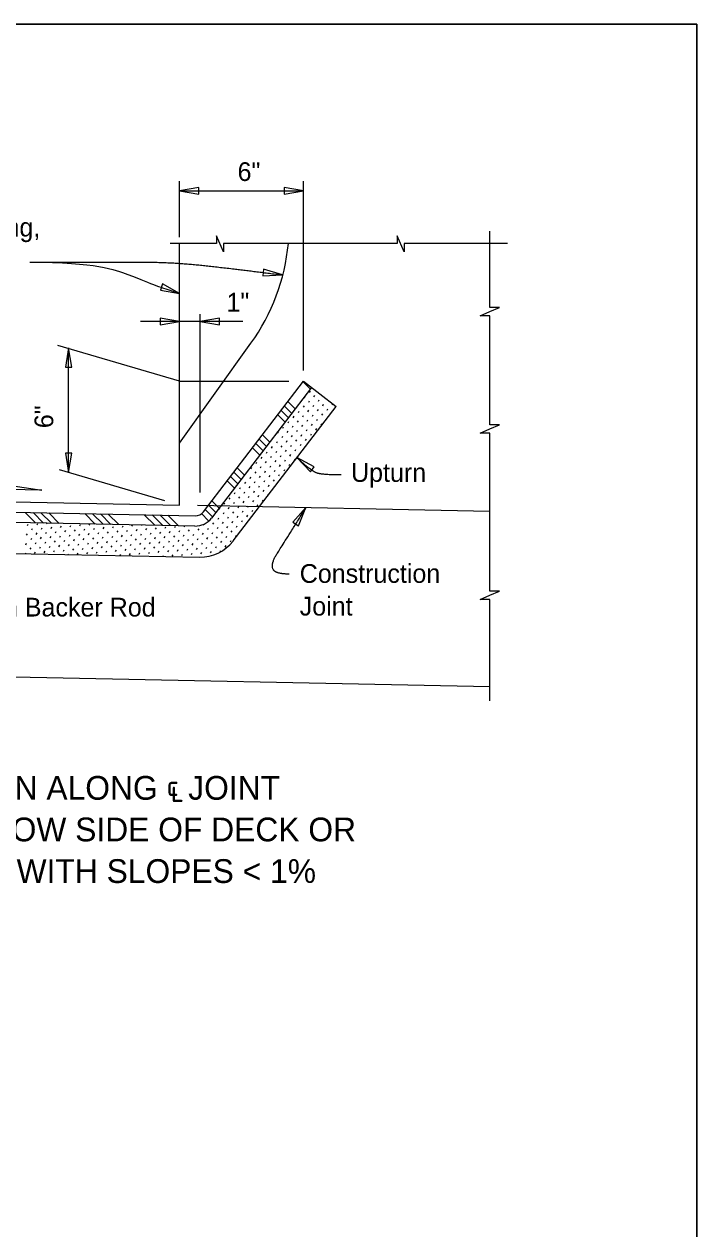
# Model space of a CAD drawing. Extents: x 0 to 15.4, y 0 to 9.7.
# Drawn here: x 12.677 to 15.394, y 4.865 to 9.73 of the extents above; entities that cross this region are included whole.
import ezdxf

# ---------------------------------------------------------------- set-up
doc = ezdxf.new("R2010")
doc.units = 0
for name, color, linetype in [('Dimension', 7, 'Continuous'), ('Miscellaneous', 7, 'Continuous'), ('Miscellaneous1', 7, 'Continuous'), ('SupstrConc', 7, 'Continuous'), ('SupstrConc_h', 7, 'Continuous'), ('TextStructures', 7, 'Continuous')]:
    doc.layers.add(name, color=color, linetype=linetype)

msp = doc.modelspace()

# ---------------------------------------------------------------- linework, layer by layer
at = {"layer": 'Dimension'}
for p, q in [((13.3048, 8.8701), (13.3048, 9.0961)), ((13.3049, 9.0564), (13.8048, 9.0564)), ((13.8048, 8.3308), (13.8048, 9.0961)), ((13.5599, 8.5291), (13.1464, 8.5291)), ((13.3883, 7.8384), (13.3883, 8.5587)), ((13.3048, 8.2874), (12.8133, 8.4319)), ((12.8566, 7.9192), (12.8566, 8.423)), ((13.3048, 8.2874), (13.7463, 8.2874)), ((13.2445, 7.8052), (12.8198, 7.93))]:
    msp.add_line(p, q, dxfattribs=at)
for points in [[(13.3048, 9.0563), (13.3829, 9.0431), (13.3829, 9.0696)], [(13.8048, 9.0563), (13.7267, 9.0696), (13.7267, 9.0431)], [(13.7197, 8.7169), (13.644, 8.74), (13.6406, 8.7137)], [(13.3048, 8.6416), (13.2361, 8.681), (13.227, 8.6561)], [(13.3048, 8.5291), (13.2267, 8.5423), (13.2267, 8.5159)], [(13.3881, 8.5291), (13.4662, 8.5159), (13.4662, 8.5423)], [(12.8565, 8.423), (12.8433, 8.3449), (12.8697, 8.3449)], [(12.8565, 7.9192), (12.8697, 7.9973), (12.8433, 7.9973)], [(13.7786, 7.9792), (13.8328, 7.9214), (13.8488, 7.9425)], [(13.8152, 7.7772), (13.7625, 7.7181), (13.7849, 7.704)]]:
    msp.add_lwpolyline(points, close=True, dxfattribs=at)
for points in [[(13.9956, 8.8435), (13.4825, 8.8435), (13.4825, 8.8104), (13.4542, 8.8744), (13.4542, 8.8435), (13.2667, 8.8435)], [(14.6286, 8.8435), (14.2115, 8.8435), (14.2115, 8.8104), (14.1831, 8.8744), (14.1831, 8.8435), (13.9956, 8.8435)], [(14.5575, 8.3416), (14.5575, 8.5521), (14.5188, 8.5521), (14.5575, 8.569), (14.5963, 8.5858), (14.5575, 8.5858), (14.5575, 8.893)], [(14.5575, 7.8014), (14.5575, 8.0783), (14.5188, 8.0783), (14.5575, 8.0952), (14.5963, 8.1121), (14.5575, 8.1121), (14.5575, 8.3416)], [(12.3088, 7.8559), (12.3453, 7.9083), (12.7488, 7.8484), (11.5452, 7.8725)], [(14.5575, 6.9971), (14.5575, 7.4067), (14.5188, 7.4067), (14.5575, 7.4235), (14.5963, 7.4404), (14.5575, 7.4404), (14.5575, 7.8014)]]:
    msp.add_lwpolyline(points, dxfattribs=at)
for points, degree in [([(12.6999, 8.7689), (13.0172, 8.7689), (13.2759, 8.7689), (13.529, 8.7414), (13.7197, 8.7169)], 2), ([(12.6999, 8.7689), (12.9693, 8.7674), (13.1155, 8.7122), (13.2151, 8.67), (13.2581, 8.6581), (13.3048, 8.6416)], 3), ([(13.9576, 7.9093), (13.886, 7.9093), (13.8377, 7.9228), (13.7786, 7.9791)], 2), ([(13.7473, 7.509), (13.6887, 7.509), (13.6736, 7.5524), (13.7227, 7.6299), (13.8153, 7.7772)], 2)]:
    msp.add_open_spline(points, degree=degree, dxfattribs=at)
at = {"layer": 'Miscellaneous'}
for p, q in [((13.4011, 7.7608), (13.8049, 8.2874)), ((13.8036, 8.2858), (13.8334, 8.2561)), ((13.8049, 8.2874), (13.9372, 8.186)), ((13.838, 8.262), (13.4342, 7.7354)), ((13.8087, 8.2211), (13.812, 8.2267)), ((13.8297, 8.242), (13.8329, 8.2476)), ((13.8474, 8.2243), (13.8507, 8.2299)), ((13.5205, 7.6426), (13.9372, 8.186)), ((13.7284, 8.1877), (13.7581, 8.1579)), ((13.7419, 8.2053), (13.7717, 8.1756)), ((13.8055, 8.1824), (13.8087, 8.188)), ((13.8265, 8.2034), (13.8297, 8.209)), ((13.8442, 8.1857), (13.8474, 8.1913)), ((13.8619, 8.1679), (13.8651, 8.1735)), ((13.8651, 8.2066), (13.8684, 8.2122)), ((13.8828, 8.1889), (13.8861, 8.1945)), ((13.9006, 8.1712), (13.9038, 8.1768)), ((13.9038, 8.2099), (13.9045, 8.211)), ((13.9215, 8.1921), (13.9239, 8.1962)), ((13.7013, 8.1524), (13.7311, 8.1226)), ((13.7149, 8.17), (13.7446, 8.1403)), ((13.7426, 8.1195), (13.7459, 8.1251)), ((13.7636, 8.1405), (13.7668, 8.1461)), ((13.7813, 8.1228), (13.7846, 8.1284)), ((13.7846, 8.1615), (13.7878, 8.1671)), ((13.8023, 8.1437), (13.8055, 8.1493)), ((13.82, 8.126), (13.8232, 8.1316)), ((13.8232, 8.1647), (13.8265, 8.1703)), ((13.8409, 8.147), (13.8442, 8.1526)), ((13.8586, 8.1293), (13.8619, 8.1349)), ((13.8796, 8.1502), (13.8828, 8.1558)), ((13.7007, 8.0776), (13.704, 8.0832)), ((13.7217, 8.0986), (13.7249, 8.1042)), ((13.7394, 8.0809), (13.7426, 8.0865)), ((13.7604, 8.1018), (13.7636, 8.1074)), ((13.7781, 8.0841), (13.7813, 8.0897)), ((13.799, 8.1051), (13.8023, 8.1107)), ((13.8167, 8.0874), (13.82, 8.093)), ((13.8377, 8.1083), (13.8409, 8.1139)), ((13.8554, 8.0906), (13.8586, 8.0962)), ((13.8764, 8.1116), (13.8796, 8.1172)), ((13.6125, 8.0366), (13.6423, 8.0068)), ((13.6261, 8.0542), (13.6558, 8.0245)), ((13.6396, 8.0719), (13.6694, 8.0421)), ((13.6975, 8.039), (13.7007, 8.0446)), ((13.7184, 8.0599), (13.7217, 8.0655)), ((13.7362, 8.0422), (13.7394, 8.0478)), ((13.7539, 8.0245), (13.7571, 8.0301)), ((13.7571, 8.0632), (13.7604, 8.0688)), ((13.7748, 8.0454), (13.7781, 8.051)), ((13.7925, 8.0277), (13.7958, 8.0333)), ((13.7958, 8.0664), (13.799, 8.072)), ((13.8135, 8.0487), (13.8167, 8.0543)), ((13.8345, 8.0696), (13.8377, 8.0752)), ((13.599, 8.0189), (13.6287, 7.9892)), ((13.6346, 7.9761), (13.6379, 7.9817)), ((13.6556, 7.9971), (13.6588, 8.0027)), ((13.6733, 7.9793), (13.6765, 7.9849)), ((13.6765, 8.018), (13.6798, 8.0236)), ((13.6942, 8.0003), (13.6975, 8.0059)), ((13.712, 7.9826), (13.7152, 7.9882)), ((13.7152, 8.0213), (13.7184, 8.0268)), ((13.7329, 8.0035), (13.7362, 8.0091)), ((13.7506, 7.9858), (13.7539, 7.9914)), ((13.7716, 8.0068), (13.7748, 8.0124)), ((13.5373, 7.9384), (13.567, 7.9087)), ((13.5927, 7.9342), (13.596, 7.9398)), ((13.6137, 7.9551), (13.6169, 7.9607)), ((13.6314, 7.9374), (13.6346, 7.943)), ((13.6523, 7.9584), (13.6556, 7.964)), ((13.6701, 7.9407), (13.6733, 7.9463)), ((13.691, 7.9616), (13.6942, 7.9672)), ((13.7087, 7.9439), (13.712, 7.9495)), ((13.7264, 7.9262), (13.7297, 7.9318)), ((13.7297, 7.9649), (13.7329, 7.9705)), ((13.7474, 7.9472), (13.7506, 7.9528)), ((13.7683, 7.9681), (13.7716, 7.9737)), ((13.4967, 7.8854), (13.5264, 7.8557)), ((13.5102, 7.9031), (13.54, 7.8734)), ((13.5238, 7.9208), (13.5535, 7.891)), ((13.5718, 7.9132), (13.575, 7.9188)), ((13.5895, 7.8955), (13.5927, 7.9011)), ((13.6072, 7.8778), (13.6104, 7.8834)), ((13.6104, 7.9165), (13.6137, 7.9221)), ((13.6281, 7.8988), (13.6314, 7.9044)), ((13.6459, 7.881), (13.6491, 7.8866)), ((13.6491, 7.9197), (13.6523, 7.9253)), ((13.6668, 7.902), (13.6701, 7.9076)), ((13.6845, 7.8843), (13.6878, 7.8899)), ((13.6878, 7.923), (13.691, 7.9286)), ((13.7055, 7.9052), (13.7087, 7.9108)), ((13.5266, 7.8327), (13.5298, 7.8383)), ((13.5476, 7.8536), (13.5508, 7.8592)), ((13.5653, 7.8359), (13.5685, 7.8415)), ((13.5685, 7.8746), (13.5718, 7.8802)), ((13.5862, 7.8568), (13.5895, 7.8624)), ((13.6039, 7.8391), (13.6072, 7.8447)), ((13.6249, 7.8601), (13.6281, 7.8657)), ((13.6426, 7.8424), (13.6459, 7.848)), ((13.6636, 7.8633), (13.6668, 7.8689)), ((11.2373, 7.7871), (13.3672, 7.7445)), ((13.4214, 7.7873), (13.4512, 7.7576)), ((13.435, 7.805), (13.4647, 7.7752)), ((13.4847, 7.7907), (13.4879, 7.7963)), ((13.5056, 7.8117), (13.5089, 7.8173)), ((13.5234, 7.794), (13.5266, 7.7996)), ((13.5443, 7.8149), (13.5476, 7.8205)), ((13.562, 7.7972), (13.5653, 7.8028)), ((13.5797, 7.7795), (13.583, 7.7851)), ((13.583, 7.8182), (13.5862, 7.8238)), ((13.6007, 7.8005), (13.6039, 7.8061)), ((13.6184, 7.7828), (13.6217, 7.7883)), ((13.6217, 7.8214), (13.6249, 7.827)), ((13.6394, 7.8037), (13.6426, 7.8093)), ((13.6609, 7.8257), (13.6636, 7.8303)), ((13.3664, 7.7028), (11.2373, 7.7454)), ((12.6808, 7.7582), (12.7234, 7.7156)), ((12.7127, 7.7576), (12.7552, 7.715)), ((12.7445, 7.7569), (12.7871, 7.7144)), ((12.7763, 7.7563), (12.8189, 7.7137)), ((12.9214, 7.7534), (12.964, 7.7108)), ((12.9532, 7.7527), (12.9958, 7.7102)), ((12.9851, 7.7521), (13.0276, 7.7095)), ((13.0169, 7.7515), (13.0595, 7.7089)), ((13.162, 7.7486), (13.2046, 7.706)), ((13.1938, 7.7479), (13.2364, 7.7054)), ((13.2257, 7.7473), (13.2682, 7.7047)), ((13.2575, 7.7467), (13.3001, 7.7041)), ((13.3929, 7.7534), (13.4218, 7.7246)), ((13.4079, 7.7697), (13.4376, 7.7399)), ((13.4605, 7.7311), (13.4637, 7.7367)), ((13.4637, 7.7698), (13.467, 7.7754)), ((13.4815, 7.7521), (13.4847, 7.7577)), ((13.4992, 7.7344), (13.5024, 7.74)), ((13.5024, 7.773), (13.5056, 7.7786)), ((13.5201, 7.7553), (13.5234, 7.7609)), ((13.5378, 7.7376), (13.5411, 7.7432)), ((13.5411, 7.7763), (13.5443, 7.7819)), ((13.5588, 7.7586), (13.562, 7.7642)), ((13.5765, 7.7408), (13.5797, 7.7464)), ((13.5975, 7.7618), (13.6007, 7.7674)), ((12.6903, 7.705), (12.6936, 7.7106)), ((12.7081, 7.6873), (12.7113, 7.6929)), ((12.729, 7.7082), (12.7323, 7.7138)), ((12.7467, 7.6905), (12.75, 7.6961)), ((12.7677, 7.7115), (12.7696, 7.7147)), ((12.7854, 7.6937), (12.7886, 7.6993)), ((12.8241, 7.697), (12.8273, 7.7026)), ((12.8627, 7.7002), (12.866, 7.7058)), ((12.8804, 7.6825), (12.8837, 7.6881)), ((12.9014, 7.7035), (12.9046, 7.7091)), ((12.9191, 7.6857), (12.9224, 7.6913)), ((12.9401, 7.7067), (12.9427, 7.7112)), ((12.9578, 7.689), (12.961, 7.6946)), ((12.9787, 7.7099), (12.9791, 7.7105)), ((12.9965, 7.6922), (12.9997, 7.6978)), ((13.0351, 7.6955), (13.0384, 7.7011)), ((13.0738, 7.6987), (13.077, 7.7043)), ((13.0915, 7.681), (13.0948, 7.6866)), ((13.1125, 7.7019), (13.1157, 7.7075)), ((13.1302, 7.6842), (13.1334, 7.6898)), ((13.1511, 7.7052), (13.1522, 7.7071)), ((13.1689, 7.6875), (13.1721, 7.6931)), ((13.2075, 7.6907), (13.2108, 7.6963)), ((13.2462, 7.694), (13.2494, 7.6996)), ((13.2849, 7.6972), (13.2881, 7.7028)), ((13.3235, 7.7004), (13.3254, 7.7036)), ((13.3412, 7.6827), (13.3445, 7.6883)), ((13.3799, 7.686), (13.3832, 7.6916)), ((13.4009, 7.7069), (13.4029, 7.7105)), ((13.4186, 7.6892), (13.4218, 7.6948)), ((13.4395, 7.7102), (13.4428, 7.7158)), ((13.4573, 7.6924), (13.4605, 7.698)), ((13.4782, 7.7134), (13.4815, 7.719)), ((13.4959, 7.6957), (13.4992, 7.7013)), ((13.5169, 7.7166), (13.5201, 7.7222)), ((13.5346, 7.6989), (13.5378, 7.7045)), ((13.5556, 7.7199), (13.5588, 7.7255)), ((12.6871, 7.6663), (12.6903, 7.6719)), ((12.7048, 7.6486), (12.7081, 7.6542)), ((12.7258, 7.6695), (12.729, 7.6751)), ((12.7435, 7.6518), (12.7467, 7.6574)), ((12.7612, 7.6341), (12.7644, 7.6397)), ((12.7644, 7.6728), (12.7677, 7.6784)), ((12.7822, 7.6551), (12.7854, 7.6607)), ((12.7999, 7.6374), (12.8031, 7.6429)), ((12.8031, 7.676), (12.8063, 7.6816)), ((12.8208, 7.6583), (12.8241, 7.6639)), ((12.8385, 7.6406), (12.8418, 7.6462)), ((12.8418, 7.6793), (12.845, 7.6849)), ((12.8595, 7.6615), (12.8627, 7.6671)), ((12.8772, 7.6438), (12.8804, 7.6494)), ((12.8982, 7.6648), (12.9014, 7.6704)), ((12.9159, 7.6471), (12.9191, 7.6527)), ((12.9368, 7.668), (12.9401, 7.6736)), ((12.9545, 7.6503), (12.9578, 7.6559)), ((12.9723, 7.6326), (12.9755, 7.6382)), ((12.9755, 7.6713), (12.9787, 7.6769)), ((12.9932, 7.6536), (12.9965, 7.6592)), ((13.0109, 7.6358), (13.0142, 7.6414)), ((13.0142, 7.6745), (13.0174, 7.6801)), ((13.0319, 7.6568), (13.0351, 7.6624)), ((13.0496, 7.6391), (13.0528, 7.6447)), ((13.0528, 7.6778), (13.0561, 7.6834)), ((13.0706, 7.66), (13.0738, 7.6656)), ((13.0883, 7.6423), (13.0915, 7.6479)), ((13.1092, 7.6633), (13.1125, 7.6689)), ((13.1269, 7.6456), (13.1302, 7.6512)), ((13.1479, 7.6665), (13.1511, 7.6721)), ((13.1656, 7.6488), (13.1689, 7.6544)), ((13.1866, 7.6698), (13.1898, 7.6754)), ((13.2043, 7.652), (13.2075, 7.6576)), ((13.222, 7.6343), (13.2252, 7.6399)), ((13.2252, 7.673), (13.2285, 7.6786)), ((13.243, 7.6553), (13.2462, 7.6609)), ((13.2607, 7.6376), (13.2639, 7.6432)), ((13.2639, 7.6762), (13.2671, 7.6818)), ((13.2816, 7.6585), (13.2849, 7.6641)), ((13.2993, 7.6408), (13.3026, 7.6464)), ((13.3026, 7.6795), (13.3058, 7.6851)), ((13.3203, 7.6618), (13.3235, 7.6674)), ((13.338, 7.6441), (13.3412, 7.6497)), ((13.359, 7.665), (13.3622, 7.6706)), ((13.3767, 7.6473), (13.3799, 7.6529)), ((13.3976, 7.6683), (13.4009, 7.6738)), ((13.4153, 7.6505), (13.4186, 7.6561)), ((13.4331, 7.6328), (13.4363, 7.6384)), ((13.4363, 7.6715), (13.4395, 7.6771)), ((13.454, 7.6538), (13.4573, 7.6594)), ((13.4717, 7.6361), (13.475, 7.6417)), ((13.475, 7.6747), (13.4782, 7.6803)), ((13.4927, 7.657), (13.4959, 7.6626)), ((13.5104, 7.6393), (13.5136, 7.6449)), ((13.5136, 7.678), (13.5169, 7.6836)), ((13.5314, 7.6603), (13.5346, 7.6659)), ((11.2373, 7.6204), (13.3849, 7.5774)), ((12.6821, 7.5914), (12.6839, 7.5946)), ((12.6839, 7.6276), (12.6871, 7.6332)), ((12.7016, 7.6099), (12.7048, 7.6155)), ((12.7193, 7.5922), (12.7225, 7.5978)), ((12.7225, 7.6309), (12.7258, 7.6365)), ((12.7402, 7.6132), (12.7435, 7.6188)), ((12.758, 7.5954), (12.7612, 7.601)), ((12.7789, 7.6164), (12.7822, 7.622)), ((12.7966, 7.5987), (12.7999, 7.6043)), ((12.8176, 7.6196), (12.8208, 7.6252)), ((12.8353, 7.6019), (12.8385, 7.6075)), ((12.8552, 7.588), (12.8563, 7.5898)), ((12.8563, 7.6229), (12.8595, 7.6285)), ((12.874, 7.6052), (12.8772, 7.6108)), ((12.8917, 7.5874), (12.8949, 7.593)), ((12.8949, 7.6261), (12.8982, 7.6317)), ((12.9126, 7.6084), (12.9159, 7.614)), ((12.9304, 7.5907), (12.9336, 7.5963)), ((12.9336, 7.6294), (12.9368, 7.635)), ((12.9513, 7.6116), (12.9545, 7.6172)), ((12.969, 7.5939), (12.9723, 7.5995)), ((12.99, 7.6149), (12.9932, 7.6205)), ((13.0077, 7.5972), (13.0109, 7.6028)), ((13.0286, 7.6181), (13.0319, 7.6237)), ((13.0464, 7.6004), (13.0496, 7.606)), ((13.0673, 7.6214), (13.0706, 7.627)), ((13.085, 7.6037), (13.0883, 7.6093)), ((13.1027, 7.5859), (13.106, 7.5915)), ((13.106, 7.6246), (13.1092, 7.6302)), ((13.1237, 7.6069), (13.1269, 7.6125)), ((13.1414, 7.5892), (13.1447, 7.5948)), ((13.1447, 7.6278), (13.1479, 7.6334)), ((13.1624, 7.6101), (13.1656, 7.6157)), ((13.1801, 7.5924), (13.1833, 7.598)), ((13.1833, 7.6311), (13.1866, 7.6367)), ((13.201, 7.6134), (13.2043, 7.619)), ((13.2188, 7.5957), (13.222, 7.6013)), ((13.2397, 7.6166), (13.243, 7.6222)), ((13.2574, 7.5989), (13.2607, 7.6045)), ((13.2784, 7.6199), (13.2816, 7.6255)), ((13.2961, 7.6021), (13.2993, 7.6077)), ((13.3138, 7.5844), (13.317, 7.59)), ((13.317, 7.6231), (13.3203, 7.6287)), ((13.3348, 7.6054), (13.338, 7.611)), ((13.3525, 7.5877), (13.3557, 7.5933)), ((13.3557, 7.6263), (13.359, 7.6319)), ((13.3734, 7.6086), (13.3767, 7.6142)), ((13.3911, 7.5909), (13.3944, 7.5965)), ((13.3944, 7.6296), (13.3976, 7.6352)), ((13.4121, 7.6119), (13.4153, 7.6175)), ((13.4298, 7.5942), (13.4331, 7.5997)), ((13.4508, 7.6151), (13.454, 7.6207)), ((13.469, 7.5983), (13.4717, 7.603)), ((13.4894, 7.6183), (13.4927, 7.6239)), ((13.0283, 7.5845), (13.0286, 7.5851)), ((13.0647, 7.5838), (13.0673, 7.5883)), ((13.2378, 7.5803), (13.2397, 7.5835)), ((13.2751, 7.5812), (13.2784, 7.5868))]:
    msp.add_line(p, q, dxfattribs=at)
msp.add_lwpolyline([(0, 0), (15.394, 0), (15.394, 9.7298), (0, 9.7298)], close=True, dxfattribs=at)
for centre, radius in [((13.368, 7.7861), 0.0833), ((13.368, 7.7862), 0.0417), ((13.3883, 7.744), 0.1667)]:
    msp.add_arc(centre, radius, 268.8533, 322.5215, dxfattribs=at)
at = {"layer": 'Miscellaneous1'}
msp.add_lwpolyline([(0, 9.7298), (15.394, 9.7298), (15.394, 0), (0, 0)], close=True, dxfattribs=at)
at = {"layer": 'SupstrConc'}
for p, q in [((13.3048, 8.0374), (13.3048, 8.8435)), ((13.3048, 8.0374), (13.5931, 8.441)), ((13.3048, 7.7874), (13.3048, 8.0374)), ((11.423, 7.8251), (13.3049, 7.7874)), ((14.5576, 7.0541), (11.2372, 7.1205))]:
    msp.add_line(p, q, dxfattribs=at)
msp.add_arc((12.915, 8.9253), 0.8333, 324.4623, 354.3636, dxfattribs=at)
at = {"layer": 'SupstrConc_h'}
msp.add_line((14.5576, 7.7623), (13.3764, 7.786), dxfattribs=at)

# ---------------------------------------------------------------- texts
at = {"layer": 'Dimension'}
for s, height, p in [('Face of Traffic Railing, ', 0.0756, (11.731, 8.8718)), ('Construction ', 0.0756, (13.7899, 7.4736)), ('Joint', 0.0756, (13.7899, 7.3416)), ('PARTIAL SECTION ALONG ℄ JOINT', 0.096, (11.5898, 6.5978)), ('JOINT TREATMENT AT LOW SIDE OF DECK OR', 0.096, (11.1287, 6.4298)), ('HIGH SIDE OF DECK WITH SLOPES < 1%', 0.096, (11.3483, 6.2618))]:
    msp.add_text(s, height=height, dxfattribs=at).set_placement(p)
at = {"layer": 'TextStructures'}
for s, p in [('6"', (13.5389, 9.0963)), ('1"', (13.4941, 8.5691)), ('Upturn', (13.9971, 7.8813)), ('Foam Backer Rod', (12.3932, 7.3377))]:
    msp.add_text(s, height=0.0756, dxfattribs=at).set_placement(p)
msp.add_text('6"', height=0.0756, rotation=90, dxfattribs=at).set_placement((12.7945, 8.0981))

doc.saveas('drawing.dxf')
